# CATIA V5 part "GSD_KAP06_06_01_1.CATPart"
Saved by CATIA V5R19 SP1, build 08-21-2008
Part number: GSD_OFFSET_03
Definition: Beispielmodell für Funktionen Übergang, Füllen und Offset.
Description: CATIA V5 Flächenmodellierung  Copyright (c) 2009 Maik Hertha IT Consultants
Bounding box of the stored display mesh (mm): x 0 to 49.234, y -0.206 to 47.42, z 0 to 65.132
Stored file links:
  \GSD_BUCH_UEBUNG\GSD_KAP06_06_01_1.CATPart
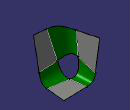
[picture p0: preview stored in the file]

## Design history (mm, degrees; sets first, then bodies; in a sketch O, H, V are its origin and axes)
AxisSystem1 "Absolute Axis System": origin (0, 0, 0), X (1, 0, 0), Y (0, 1, 0), Z (0, 0, 1)
Set1 "Planes.1"
  Plane1: type Equation, A 0, B 1, C 0, Length 0
  Plane2: type Equation, A 0, B 0, C 1, Length 0
  Plane3: type Equation, A 1, B 0, C 0, Length 0
Set2 "Skizzen.1"
  Sketch1 on Plane1, origin (0, 0, 0), H (-1, 0, 0), V (0, 0, 1)
    line L1 (-40.7892, 13.7277) -> (-49.2341, 65.1316)
    line L2 (-49.2341, 65.1316) -> (-29.5293, 63.051)
    line L3 (-29.5293, 63.051) -> (-14.1082, 15.4412)
    line L4 (-14.1082, 15.4412) -> (-40.7892, 13.7277)
  Sketch2 on Plane3, origin (0, 0, 0), H (0, 1, 0), V (0, 0, 1)
    line L1 (16.0881, 21.2572) -> (13.3955, 53.2011)
    line L2 (13.3955, 53.2011) -> (47.42, 60.6669)
    line L3 (47.42, 60.6669) -> (41.3005, 12.9347)
    line L4 (41.3005, 12.9347) -> (16.0881, 21.2572)
  Sketch3 on Plane2, origin (0, 0, 0), H (1, 0, 0), V (0, 1, 0)
    line L1 (12.7396, 17.2746) -> (9.9246, 38.9377)
    line L2 (9.9246, 38.9377) -> (44.561, 39.7944)
    line L3 (44.561, 39.7944) -> (41.746, 12.379)
    line L4 (41.746, 12.379) -> (12.7396, 17.2746)
Set3 "Basisflaechen.1"
  Split1: ToCut Plane1, Cutting Sketch1
  Split2: ToCut Plane3, Cutting Sketch2
  Split3: ToCut Plane2, Cutting Sketch3
Set4 "Blends"
  Boundary1: Boundary edge of Split1
  Boundary2: Boundary edge of Split3
  Boundary3: Boundary edge of Split1
  Boundary4: Boundary edge of Split2
  Boundary5: Boundary edge of Split2
  Boundary6: Boundary edge of Split3
  Blend1: StartLimit {blendlimit Support Split3, Curve Boundary2}, EndLimit {blendlimit Support Split1, Curve Boundary1}
  Blend2: StartLimit {blendlimit Support Split1, Curve Boundary3}, EndLimit {blendlimit Support Split2, Curve Boundary4}
  Blend3: StartLimit {blendlimit Support Split2, Curve Boundary5}, EndLimit {blendlimit Support Split3, Curve Boundary6}
Body1 (main body)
